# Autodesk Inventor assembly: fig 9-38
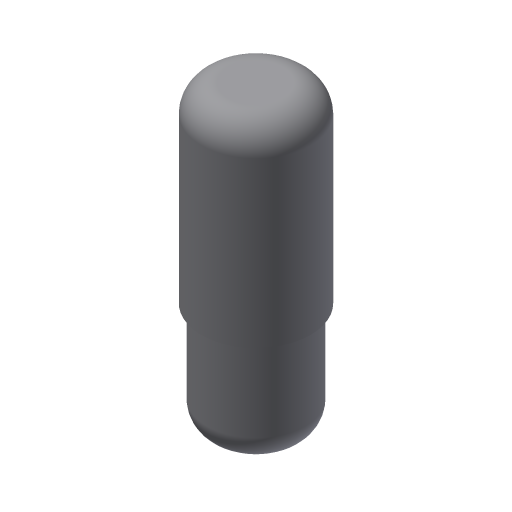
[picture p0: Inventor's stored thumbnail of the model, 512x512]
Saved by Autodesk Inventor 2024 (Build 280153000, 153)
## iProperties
Created: 2013-07
Part Number: fig 9-38
Document SubType Name: Assembly
Designer: CADCIM
Author: CADCIM
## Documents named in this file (3)
- D:\PROJECTS\Project 2023\RESOURCES INVENTOR 2024\RESOURCES INVENTOR 2024\Inventor_2023_Part\Inventor_2024_Part\c09_Inv_2024_prt\fig 9-39.iam
- D:\PROJECTS\Project 2023\RESOURCES INVENTOR 2024\RESOURCES INVENTOR 2024\Inventor_2023_Part\Inventor_2024_Part\c09_Inv_2024_prt\10.ipt
- D:\PROJECTS\Project 2023\RESOURCES INVENTOR 2024\RESOURCES INVENTOR 2024\Inventor_2023_Part\Inventor_2024_Part\c09_Inv_2024_prt\11.ipt
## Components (2 placed, 2 different names)
1. 10:1 — Rigid:1
2. 11:1 — Rigid:1
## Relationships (1: WeldJoint 1)
- Rigid:1 [WeldJoint]: 10:1 ↔ 11:1
